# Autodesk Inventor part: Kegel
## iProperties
Created: 2009-11
Part Number: Kegel
Document SubType Name: Blech
Designer: EH
Mass: 24.8378 g
Surface Area: 138.262 cm^2
Volume: 24.8378 cm^3
Density: 1 g/cm^3
Flat Pattern Width: 10.9974 cm
Flat Pattern Length: 10.6597 cm
Flat Pattern Area: 117.228 cm^2
Sheet Metal Rule: Standard
Author: EH
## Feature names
1. Trennen1
